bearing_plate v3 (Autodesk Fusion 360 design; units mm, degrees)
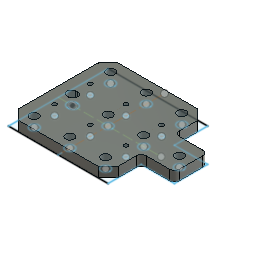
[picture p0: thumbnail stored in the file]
parameter "separation" = 43
parameter "hole_01" = 5.2
sketch "Sketch1" plane through (0, 0, 0) normal (0, 1, 0) x axis (1, 0, 0)
  line L1 (10, 25) -> (-50, 25)
  line L2 (-50, -35) -> (10, -35)
  line L3 (-50, 25) -> (-50, -35)
  line L4 (-20, -33) -> (-20, -35)
  line L5 (-20, 29) -> (-20, -33)
  line L6 (12, -5) -> (-50, -5)
  line L7 (30, 5) -> (10, 5)
  line L8 (30, -15) -> (30, 5)
  line L9 (10, -15) -> (30, -15)
  line L10 (10, 5) -> (10, 25)
  line L11 (10, -35) -> (10, -15)
  line L12 (-41, -7.6) -> (-42, -7.6)
  line L13 (-42, -2.4) -> (-41, -2.4)
  line L14 (-41, -5) -> (-42, -5)
  circle C1 centre (-41.5, -28) radius 2.6
  circle C2 centre (-41.5, -15.75) radius 1.25
  circle C3 centre (-20, -15.75) radius 1.25
  circle C4 centre (1.5, -15.75) radius 1.25
  circle C5 centre (-41.5, 5.75) radius 1.25
  circle C6 centre (-20, 5.75) radius 1.25
  circle C7 centre (1.5, 5.75) radius 1.25
  circle C8 centre (23, -5) radius 2.6
  circle C9 centre (-20, -28) radius 2.6
  circle C10 centre (1.5, -28) radius 2.6
  circle C11 centre (-20, -5) radius 2.6
  circle C12 centre (1.5, -5) radius 2.6
  circle C13 centre (-41.5, 18) radius 2.6
  circle C14 centre (-20, 18) radius 2.6
  circle C15 centre (1.5, 18) radius 2.6
  arc A1 centre (-41, -5) radius 2.6 clockwise from (-41, -2.4) to (-41, -7.6)
  arc A2 centre (-42, -5) radius 2.6 clockwise from (-42, -7.6) to (-42, -2.4)
  point P6 (-20, -35)
  point P9 (-50, -5)
  point P35 (-41, -5)
  point P36 (-41.5, -5)
  point P2 (-50, 25)
  point P5 (-50, -35)
  point P3 (10, 25)
  point P11 (-41.5, -28)
  point P12 (-41.5, -15.75)
  point P19 (30, 5)
  point P20 (30, -15)
  point P21 (10, -15)
  horizontal L1
  vertical L10
  horizontal L2
  vertical L3
  midpoint L2 P6
  perpendicular L2 L4
  perpendicular L1 L5
  midpoint L3 P9
  horizontal L7
  vertical L8
  horizontal L9
  collinear L10 L11
  tangent L12 A1
  tangent A1 L13
  parallel L12 L13
  tangent L13 A2
  tangent L12 A2
  coincident L6 P35
  parallel L6 L14
  midpoint L14 P36
  dimension "d1" distance P2 P5 = 60
  dimension "d2" distance P2 P3 = 60
  dimension "d21" diameter C1 = 5.2 (= "hole_01")
  dimension "d22" distance L5 P11 = 21.5 (= "separation / 2")
  dimension "d28" diameter C2 = 2.5
  dimension "d29" distance L5 P12 = 21.5 (= "separation / 2")
  dimension "d35" distance P19 P20 = 20
  dimension "d36" distance P20 P21 = 20
  dimension "d38" diameter C8 = 5.2 (= "hole_01")
  dimension "d48" distance L6 P11 = 23
  dimension "d33" R-Pattern2-uDistance = 21.5 (= "separation / 2")
  dimension "d34" R-Pattern2-vDistance = 21.5 (= "separation / 2")
  dimension "d46" R-Pattern2-uDistance = 21.5 (= "separation / 2")
  dimension "d47" R-Pattern2-vDistance = 23
extrude "Extrude1" new body sketch "Sketch1" profile of L1 L11 L2 L3 C1 C2 C3 C4 C5 C6 C7 L7 L8 L9 C8 C9 C10 C11 C12 C13 C14 C15 L12 A1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 along normal blind 6
chamfer "Chamfer1" distance 6
fillet "Fillet1" radius 3
fillet "Fillet2" radius 3
sketch "Sketch6" plane through (0, 6, 0) normal (0, 1, 0) x axis (-1, 0, 0)
  line L1 (-13, -5) -> (-27, -5)
  line L2 (-10, -19) -> (-10, -8)
  line L3 (-4, -25) -> (-10, -19)
  line L4 (44, -25) -> (-4, -25)
  line L5 (50, -19) -> (44, -25)
  line L6 (50, 29) -> (50, -19)
  line L7 (44, 35) -> (50, 29)
  line L8 (-4, 35) -> (44, 35)
  line L9 (-10, 29) -> (-4, 35)
  line L10 (-10, 18) -> (-10, 29)
  line L11 (-27, 15) -> (-13, 15)
  line L12 (-30, -2) -> (-30, 12)
  line L13 (41, 2.4) -> (42, 2.4)
  line L14 (42, 7.6) -> (41, 7.6)
  arc A1 centre (-27, -2) radius 3 clockwise from (-27, -5) to (-30, -2)
  arc A2 centre (-13, -8) radius 3 clockwise from (-13, -5) to (-10, -8)
  arc A3 centre (-13, 18) radius 3 clockwise from (-10, 18) to (-13, 15)
  arc A4 centre (-27, 12) radius 3 clockwise from (-30, 12) to (-27, 15)
  circle C1 centre (41.5, 28) radius 2.6
  circle C2 centre (41.5, -5.75) radius 1.25
  circle C3 centre (41.5, 15.75) radius 1.25
  circle C4 centre (20, 15.75) radius 1.25
  circle C5 centre (-1.5, 15.75) radius 1.25
  circle C6 centre (20, -5.75) radius 1.25
  circle C7 centre (-1.5, -5.75) radius 1.25
  circle C8 centre (-23, 5) radius 2.6
  circle C9 centre (20, 28) radius 2.6
  circle C10 centre (-1.5, 28) radius 2.6
  circle C11 centre (20, 5) radius 2.6
  circle C12 centre (-1.5, 5) radius 2.6
  circle C13 centre (41.5, -18) radius 2.6
  circle C14 centre (20, -18) radius 2.6
  circle C15 centre (-1.5, -18) radius 2.6
  arc A5 centre (42, 5) radius 2.6 clockwise from (42, 7.6) to (42, 2.4)
  arc A6 centre (41, 5) radius 2.6 clockwise from (41, 2.4) to (41, 7.6)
